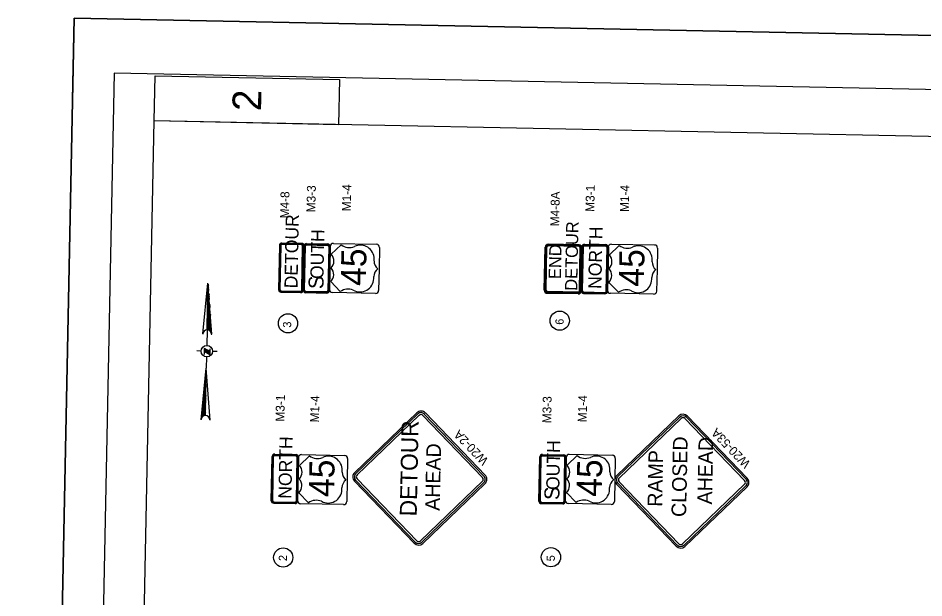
# Model space of a CAD drawing. Extents: x 335726 to 369746, y 119154 to 200788.
# Drawn here: x 335726 to 352294, y 160200 to 170808 of the extents above; entities that cross this region are included whole.
import ezdxf

# ---------------------------------------------------------------- set-up
doc = ezdxf.new("R2010")
doc.units = 0
for name, color, linetype in [('CA-TBLK', 7, 'Continuous'), ('CA-TEXT', 7, 'Continuous'), ('P_RDWY_Text', 7, 'Continuous'), ('P_SGN_Cell', 7, 'Continuous'), ('PLT_Sheet_Border', 7, 'Continuous'), ('PLT_Sheet_Info', 7, 'Continuous')]:
    doc.layers.add(name, color=color, linetype=linetype)

msp = doc.modelspace()

# ---------------------------------------------------------------- linework, layer by layer
at = {"layer": 'CA-TBLK'}
for p, q in [((339106, 165031), (339199, 165960)), ((339182, 165105), (339199, 165960)), ((339197, 165855), (339213, 165869)), ((339212, 165854), (339197, 165840)), ((339198, 165915), (339213, 165914)), ((339213, 165914), (339198, 165900)), ((339198, 165900), (339213, 165899)), ((339213, 165884), (339198, 165885)), ((339198, 165870), (339213, 165884)), ((339213, 165869), (339198, 165870)), ((339271, 165028), (339199, 165960)), ((339199, 165960), (339199, 165960)), ((339199, 165960), (339199, 165960)), ((339199, 165945), (339199, 165945)), ((339199, 165930), (339214, 165929)), ((339214, 165929), (339199, 165930)), ((339193, 165660), (339224, 165689)), ((339225, 165734), (339194, 165705)), ((339225, 165719), (339194, 165690)), ((339194, 165705), (339225, 165719)), ((339194, 165675), (339224, 165704)), ((339224, 165689), (339194, 165675)), ((339195, 165765), (339211, 165779)), ((339211, 165779), (339195, 165765)), ((339210, 165764), (339195, 165750)), ((339195, 165735), (339225, 165764)), ((339225, 165749), (339195, 165735)), ((339195, 165720), (339225, 165734)), ((339212, 165824), (339196, 165810)), ((339211, 165809), (339196, 165795)), ((339196, 165795), (339211, 165809)), ((339196, 165780), (339211, 165794)), ((339197, 165840), (339212, 165839)), ((339212, 165839), (339197, 165825)), ((339197, 165825), (339212, 165824)), ((339190, 165495), (339236, 165539)), ((339236, 165539), (339190, 165510)), ((339190, 165480), (339236, 165524)), ((339236, 165524), (339190, 165495)), ((339222, 165599), (339191, 165570)), ((339222, 165584), (339191, 165555)), ((339191, 165555), (339222, 165584)), ((339236, 165569), (339191, 165525)), ((339191, 165540), (339236, 165569)), ((339191, 165525), (339236, 165554)), ((339192, 165615), (339223, 165644)), ((339192, 165600), (339223, 165629)), ((339223, 165629), (339192, 165615)), ((339222, 165614), (339192, 165585)), ((339192, 165585), (339222, 165614)), ((339224, 165674), (339193, 165660)), ((339193, 165645), (339224, 165674)), ((339223, 165659), (339193, 165630)), ((339186, 165315), (339247, 165359)), ((339247, 165359), (339186, 165315)), ((339233, 165404), (339187, 165360)), ((339187, 165360), (339233, 165404)), ((339248, 165389), (339187, 165330)), ((339187, 165345), (339248, 165389)), ((339187, 165330), (339248, 165374)), ((339188, 165420), (339234, 165464)), ((339188, 165405), (339234, 165449)), ((339234, 165449), (339188, 165420)), ((339188, 165390), (339234, 165434)), ((339234, 165434), (339188, 165390)), ((339233, 165419), (339188, 165375)), ((339189, 165465), (339235, 165494)), ((339235, 165494), (339189, 165450)), ((339235, 165479), (339189, 165435)), ((339189, 165450), (339235, 165479)), ((339235, 165509), (339190, 165480)), ((339245, 165224), (339183, 165165)), ((339183, 165165), (339245, 165224)), ((339259, 165208), (339183, 165135)), ((339183, 165150), (339259, 165208)), ((339183, 165135), (339259, 165193)), ((339184, 165210), (339245, 165269)), ((339184, 165195), (339245, 165254)), ((339245, 165254), (339184, 165195)), ((339245, 165239), (339184, 165180)), ((339246, 165314), (339185, 165255)), ((339185, 165270), (339246, 165314)), ((339246, 165299), (339185, 165240)), ((339185, 165255), (339246, 165299)), ((339185, 165225), (339246, 165284)), ((339245, 165269), (339185, 165225)), ((339186, 165285), (339247, 165344)), ((339247, 165344), (339186, 165300)), ((339247, 165329), (339186, 165285)), ((339182, 165105), (339176, 164820)), ((339182, 165120), (339259, 165178)), ((339259, 165178), (339182, 165120)), ((339258, 165163), (339182, 165105)), ((339197, 165105), (339258, 165163)), ((339258, 165148), (339212, 165104)), ((339212, 165104), (339258, 165133)), ((339258, 165133), (339227, 165089)), ((339257, 165118), (339227, 165089)), ((339227, 165089), (339257, 165118)), ((339242, 165089), (339257, 165103)), ((339257, 165088), (339242, 165074)), ((339242, 165074), (339257, 165088)), ((339256, 165058), (339257, 165073)), ((339256, 165058), (339256, 165058)), ((339256, 165043), (339256, 165043)), ((339256, 165043), (339256, 165043)), ((339256, 165028), (339271, 165028)), ((339257, 165073), (339257, 165073)), ((339069, 164717), (338994, 164719)), ((339130, 164761), (339128, 164656)), ((339129, 164716), (339175, 164745)), ((339160, 164745), (339129, 164716)), ((339129, 164716), (339160, 164745)), ((339129, 164716), (339233, 164654)), ((339130, 164746), (339145, 164761)), ((339145, 164761), (339130, 164746)), ((339130, 164761), (339130, 164761)), ((339234, 164714), (339130, 164761)), ((339160, 164760), (339130, 164731)), ((339175, 164745), (339144, 164701)), ((339144, 164701), (339190, 164730)), ((339190, 164730), (339159, 164700)), ((339159, 164700), (339205, 164729)), ((339174, 164685), (339205, 164729)), ((339205, 164729), (339174, 164700)), ((339234, 164714), (339189, 164685)), ((339189, 164685), (339219, 164714)), ((339219, 164714), (339189, 164685)), ((339203, 164669), (339234, 164699)), ((339234, 164699), (339203, 164669)), ((339235, 164759), (339233, 164654)), ((339279, 164713), (339369, 164711)), ((339172, 164610), (339168, 164400)), ((339218, 164669), (339234, 164684)), ((339234, 164684), (339218, 164669)), ((339233, 164654), (339233, 164669)), ((339074, 163457), (339168, 164400)), ((339151, 163545), (339168, 164400)), ((339167, 164370), (339167, 164370)), ((339239, 163453), (339168, 164400)), ((339168, 164400), (339168, 164400)), ((339168, 164385), (339168, 164385)), ((339168, 164385), (339168, 164385)), ((339164, 164220), (339149, 164220)), ((339149, 164220), (339164, 164205)), ((339149, 164205), (339163, 164175)), ((339164, 164190), (339149, 164205)), ((339150, 164235), (339164, 164220)), ((339165, 164265), (339166, 164280)), ((339165, 164250), (339165, 164265)), ((339165, 164265), (339165, 164265)), ((339165, 164250), (339165, 164235)), ((339165, 164235), (339165, 164250)), ((339166, 164325), (339167, 164340)), ((339166, 164325), (339166, 164325)), ((339166, 164310), (339166, 164310)), ((339166, 164310), (339166, 164295)), ((339166, 164295), (339166, 164280)), ((339166, 164295), (339166, 164295)), ((339167, 164355), (339167, 164355)), ((339167, 164355), (339167, 164355)), ((339167, 164340), (339167, 164340)), ((339130, 164026), (339160, 163995)), ((339160, 163995), (339130, 164026)), ((339131, 164056), (339160, 164025)), ((339131, 164041), (339160, 164010)), ((339160, 164025), (339131, 164041)), ((339161, 164040), (339146, 164070)), ((339146, 164070), (339161, 164040)), ((339147, 164115), (339162, 164085)), ((339162, 164100), (339147, 164115)), ((339147, 164100), (339161, 164070)), ((339161, 164070), (339147, 164100)), ((339161, 164055), (339147, 164085)), ((339163, 164160), (339148, 164175)), ((339148, 164175), (339163, 164160)), ((339163, 164130), (339148, 164160)), ((339148, 164160), (339163, 164145)), ((339148, 164145), (339163, 164130)), ((339148, 164130), (339162, 164100)), ((339162, 164115), (339148, 164130)), ((339163, 164175), (339149, 164190)), ((339112, 163876), (339156, 163830)), ((339112, 163861), (339156, 163815)), ((339156, 163815), (339112, 163861)), ((339157, 163845), (339113, 163891)), ((339157, 163875), (339128, 163921)), ((339157, 163860), (339128, 163906)), ((339128, 163906), (339157, 163875)), ((339128, 163891), (339157, 163845)), ((339159, 163935), (339129, 163981)), ((339129, 163981), (339159, 163950)), ((339129, 163966), (339159, 163935)), ((339129, 163951), (339158, 163905)), ((339158, 163920), (339129, 163951)), ((339158, 163905), (339129, 163936)), ((339129, 163936), (339158, 163890)), ((339159, 163980), (339130, 164011)), ((339159, 163965), (339130, 163996)), ((339130, 163996), (339159, 163965)), ((339153, 163665), (339109, 163726)), ((339109, 163726), (339153, 163680)), ((339153, 163650), (339109, 163711)), ((339109, 163711), (339153, 163650)), ((339109, 163696), (339153, 163635)), ((339110, 163771), (339154, 163710)), ((339154, 163725), (339110, 163771)), ((339110, 163756), (339154, 163695)), ((339154, 163710), (339110, 163756)), ((339153, 163680), (339110, 163741)), ((339156, 163785), (339111, 163831)), ((339111, 163816), (339155, 163770)), ((339155, 163770), (339111, 163816)), ((339155, 163740), (339111, 163801)), ((339111, 163801), (339155, 163755)), ((339111, 163786), (339155, 163740)), ((339112, 163846), (339156, 163800)), ((339156, 163800), (339112, 163846)), ((339090, 163531), (339105, 163516)), ((339090, 163516), (339090, 163531)), ((339091, 163576), (339120, 163531)), ((339135, 163531), (339091, 163576)), ((339120, 163531), (339091, 163561)), ((339105, 163516), (339091, 163546)), ((339091, 163546), (339105, 163531)), ((339151, 163545), (339092, 163621)), ((339092, 163621), (339151, 163560)), ((339092, 163606), (339151, 163545)), ((339092, 163591), (339136, 163546)), ((339151, 163545), (339092, 163591)), ((339093, 163681), (339152, 163620)), ((339152, 163620), (339093, 163681)), ((339093, 163666), (339152, 163590)), ((339152, 163605), (339093, 163666)), ((339152, 163590), (339093, 163651)), ((339151, 163575), (339093, 163636)), ((339093, 163636), (339151, 163575)), ((339074, 163472), (339074, 163472)), ((339075, 163517), (339090, 163501)), ((339075, 163502), (339090, 163501)), ((339090, 163501), (339075, 163502)), ((339075, 163487), (339075, 163487)), ((339075, 163487), (339075, 163487))]:
    msp.add_line(p, q, dxfattribs=at)
msp.add_circle((339178, 164713), 104, dxfattribs=at)
for centre, start, end in [((339184, 165026), 358.8468, 178.8468), ((339184, 165026), 178.84682431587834, 178.8468298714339), ((339152, 163461), 358.8468, 178.8468), ((339152, 163461), 358.84700764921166, 358.8470132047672)]:
    msp.add_arc(centre, 78.3, start, end, dxfattribs=at)
at = {"layer": 'CA-TEXT'}
for centre in [(340662, 165223), (345633, 165272), (340575, 160939), (345472, 160944)]:
    msp.add_circle(centre, 176, dxfattribs=at)
at = {"layer": 'P_RDWY_Text'}
msp.add_lwpolyline([(335726, 119818), (336753, 170808), (369746, 170144), (368719, 119154)], close=True, dxfattribs=at)
at = {"layer": 'P_SGN_Cell'}
for p, q in [((341002, 166684), (341392, 166676)), ((341493, 166686), (342281, 166670)), ((340940, 165830), (340956, 166640)), ((340951, 165830), (340967, 166640)), ((340966, 165830), (340982, 166640)), ((341002, 166673), (341392, 166665)), ((341002, 166658), (341391, 166650)), ((341410, 166631), (341393, 165821)), ((341425, 166631), (341408, 165821)), ((341436, 166631), (341420, 165821)), ((341420, 165843), (341436, 166631)), ((341636, 166661), (341454, 166486)), ((342336, 166612), (342328, 166219)), ((342336, 166612), (342336, 166612)), ((345351, 165830), (345367, 166617)), ((345365, 165829), (345381, 166617)), ((345384, 165829), (345400, 166616)), ((345986, 166628), (345423, 166639)), ((345986, 166661), (345424, 166672)), ((345986, 166647), (345424, 166658)), ((345993, 165817), (346009, 166604)), ((346012, 165816), (346028, 166604)), ((346026, 165816), (346042, 166627)), ((346026, 165816), (346042, 166604)), ((346037, 165817), (346053, 166626)), ((346052, 165816), (346068, 166626)), ((346087, 166644), (346477, 166637)), ((346088, 166671), (346478, 166663)), ((346088, 166659), (346478, 166652)), ((346496, 166617), (346479, 165808)), ((346511, 166617), (346494, 165807)), ((346506, 165830), (346522, 166617)), ((346522, 166617), (346506, 165807)), ((346722, 166648), (346540, 166473)), ((346579, 166672), (347367, 166657)), ((347422, 166599), (347414, 166205)), ((347422, 166599), (347422, 166599)), ((342238, 166364), (342238, 166399)), ((347324, 166350), (347324, 166386)), ((342328, 166219), (342320, 165825)), ((347414, 166205), (347406, 165812)), ((342231, 166042), (342232, 166078)), ((347317, 166029), (347318, 166064)), ((341444, 165986), (341619, 165804)), ((346530, 165973), (346705, 165791)), ((340984, 165811), (341374, 165803)), ((340984, 165796), (341374, 165788)), ((340984, 165785), (341374, 165777)), ((342263, 165770), (341475, 165786)), ((345969, 165775), (345406, 165786)), ((345968, 165761), (345406, 165772)), ((345969, 165794), (345407, 165805)), ((346070, 165797), (346460, 165789)), ((346070, 165782), (346460, 165774)), ((346070, 165771), (346460, 165763)), ((347349, 165757), (346561, 165773)), ((340357, 161978), (340373, 162788)), ((340368, 161978), (340384, 162788)), ((340383, 161978), (340399, 162787)), ((340419, 162832), (340809, 162824)), ((340419, 162821), (340809, 162813)), ((340419, 162806), (340808, 162798)), ((340827, 162779), (340811, 161969)), ((340842, 162779), (340826, 161969)), ((340853, 162778), (340837, 161968)), ((340837, 161980), (340853, 162767)), ((341053, 162798), (340871, 162623)), ((340910, 162822), (341698, 162806)), ((341753, 162749), (341745, 162355)), ((341753, 162749), (341753, 162749)), ((345253, 161971), (345270, 162781)), ((345265, 161971), (345281, 162781)), ((345280, 161971), (345296, 162781)), ((345315, 162814), (345705, 162806)), ((345315, 162799), (345705, 162791)), ((345316, 162825), (345706, 162817)), ((345723, 162772), (345707, 161962)), ((345738, 162772), (345722, 161962)), ((345750, 162771), (345733, 161962)), ((345734, 161984), (345750, 162771)), ((345950, 162802), (345768, 162627)), ((345807, 162827), (346594, 162811)), ((346649, 162753), (346641, 162360)), ((346649, 162753), (346649, 162753)), ((341654, 162500), (341655, 162536)), ((346551, 162504), (346552, 162540)), ((341648, 162179), (341649, 162214)), ((341745, 162355), (341737, 161962)), ((346545, 162183), (346545, 162219)), ((346641, 162360), (346634, 161966)), ((340861, 162123), (341036, 161941)), ((345758, 162127), (345933, 161945)), ((340401, 161959), (340791, 161951)), ((340401, 161944), (340791, 161936)), ((340401, 161932), (340791, 161924)), ((341679, 161907), (340892, 161922)), ((345297, 161925), (345687, 161918)), ((345298, 161952), (345688, 161944)), ((345298, 161937), (345688, 161929)), ((346576, 161911), (345789, 161927))]:
    msp.add_line(p, q, dxfattribs=at)
for points in [[(340912, 166686), (340552, 166693)], [(340912, 166674), (340552, 166682)], [(340506, 166649), (340490, 165839)], [(340517, 166648), (340501, 165839)], [(340532, 166648), (340516, 165838)], [(340912, 166659), (340552, 166667)], [(340914, 165830), (340930, 166640)], [(340929, 165830), (340945, 166640)], [(340940, 165830), (340956, 166640)], [(340534, 165804), (340894, 165797)], [(340534, 165793), (340894, 165786)], [(340535, 165819), (340894, 165812)], [(343018, 163586), (341882, 162495)], [(343038, 163565), (341902, 162474)], [(343063, 163540), (341927, 162449)], [(344221, 162403), (343130, 163539)], [(344247, 162428), (343156, 163563)], [(344267, 162448), (343177, 163583)], [(347812, 163530), (346676, 162439)], [(347832, 163509), (346696, 162418)], [(347856, 163483), (346721, 162392)], [(349015, 162347), (347924, 163482)], [(349041, 162372), (347950, 163507)], [(349061, 162391), (347970, 163527)], [(341926, 162380), (343017, 161244)], [(341879, 162336), (342970, 161200)], [(341900, 162356), (342991, 161220)], [(343085, 161243), (344221, 162334)], [(343109, 161217), (344245, 162308)], [(343129, 161197), (344265, 162288)], [(346673, 162280), (347764, 161144)], [(346693, 162299), (347784, 161163)], [(346719, 162324), (347810, 161188)], [(347878, 161187), (349014, 162278)], [(347903, 161161), (349039, 162252)], [(347923, 161140), (349059, 162231)]]:
    msp.add_lwpolyline(points, dxfattribs=at)
for centre, radius, start, end in [((340551, 166648), 45, 88.8468, 178.8468), ((340551, 166648), 33.7, 88.8468, 178.8468), ((340911, 166641), 45, 358.8468, 88.8468), ((341001, 166639), 45, 88.8462, 178.8462), ((341391, 166631), 45, 358.8462, 88.8462), ((341492, 166629), 56.2, 88.8462, 178.8462), ((340551, 166648), 18.7, 88.8468, 178.8468), ((340911, 166641), 33.7, 358.8468, 88.8468), ((340911, 166641), 18.7, 358.8468, 88.8468), ((341001, 166639), 33.7, 88.8462, 178.8462), ((341001, 166639), 18.7, 88.8462, 178.8462), ((341391, 166631), 18.7, 358.8462, 88.8462), ((341391, 166631), 33.7, 358.8462, 88.8462), ((341786, 166861), 250, 233.1143, 291.9873), ((341988, 166404), 250, 358.8462, 115.6928), ((342280, 166614), 56.2, 358.8462, 88.8462), ((345423, 166616), 56.2, 88.8468, 178.8468), ((345423, 166616), 42.2, 88.8468, 178.8468), ((345423, 166616), 23.4, 88.8468, 178.8468), ((345985, 166605), 56.2, 358.8468, 88.8468), ((345985, 166605), 42.2, 358.8468, 88.8468), ((345985, 166605), 23.4, 358.8468, 88.8468), ((346087, 166626), 45, 88.8462, 178.8462), ((346087, 166626), 33.7, 88.8462, 178.8462), ((346087, 166626), 18.7, 88.8462, 178.8462), ((346477, 166618), 18.7, 358.8462, 88.8462), ((346477, 166618), 45, 358.8462, 88.8462), ((346477, 166618), 33.7, 358.8462, 88.8462), ((346578, 166616), 56.2, 88.8462, 178.8462), ((346872, 166848), 250, 233.1143, 291.9873), ((347074, 166391), 250, 358.8462, 115.6928), ((347366, 166600), 56.2, 358.8462, 88.8462), ((341324, 166364), 179, 314.4191, 43.2734), ((342418, 166361), 181, 179.1885, 231.634), ((346410, 166351), 179, 314.4191, 43.2734), ((347504, 166348), 181, 179.1885, 231.634), ((341319, 166114), 179, 314.4191, 43.2734), ((342413, 166073), 181, 126.0584, 178.5039), ((346405, 166101), 179, 314.4191, 43.2734), ((347498, 166060), 181, 126.0584, 178.5039), ((341981, 166047), 250, 240.0981, 358.8463), ((347067, 166034), 250, 240.0981, 358.8463), ((341762, 165599), 250, 67.7159, 124.7982), ((340535, 165838), 45, 178.8468, 268.8468), ((340535, 165838), 33.7, 178.8468, 268.8468), ((340535, 165838), 18.7, 178.8468, 268.8468), ((340535, 165838), 18.7, 178.8468, 186.1883), ((340895, 165831), 45, 268.8468, 358.8468), ((340895, 165831), 33.7, 268.8468, 358.8468), ((340895, 165831), 18.7, 268.8468, 358.8468), ((340985, 165829), 45, 179.6119, 268.8462), ((340985, 165829), 33.7, 178.8462, 268.8462), ((340985, 165829), 18.7, 178.8462, 268.8462), ((341375, 165822), 33.7, 268.8462, 358.8462), ((341375, 165822), 18.7, 268.8462, 358.8462), ((341375, 165822), 45, 268.8462, 358.8462), ((341476, 165842), 56.2, 178.8462, 268.8462), ((342264, 165826), 56.2, 268.8462, 358.8462), ((345407, 165829), 56.2, 178.8468, 268.8468), ((345407, 165829), 42.2, 178.8468, 268.8468), ((345407, 165829), 23.4, 178.8468, 268.8468), ((345407, 165829), 23.4, 178.8468, 187.6911), ((345970, 165817), 56.2, 268.8468, 358.8468), ((345970, 165817), 23.4, 268.8468, 358.8468), ((345970, 165817), 42.2, 268.8468, 358.8468), ((346071, 165816), 45, 179.6119, 268.8462), ((346071, 165816), 33.7, 178.8462, 268.8462), ((346071, 165816), 18.7, 178.8462, 268.8462), ((346461, 165808), 18.7, 268.8462, 358.8462), ((346461, 165808), 33.7, 268.8462, 358.8462), ((346461, 165808), 45, 268.8462, 358.8462), ((346562, 165829), 56.2, 178.8462, 268.8462), ((346848, 165586), 250, 67.7159, 124.7982), ((347350, 165813), 56.2, 268.8462, 358.8462), ((343096, 163505), 112, 43.8468, 133.8468), ((343096, 163505), 83.9, 43.8468, 133.8468), ((343096, 163505), 48.2, 43.8468, 133.8468), ((347890, 163448), 112, 43.8462, 133.8462), ((347890, 163448), 83.9, 43.8462, 133.8462), ((347890, 163448), 48.2, 43.8462, 133.8462), ((340418, 162787), 45, 88.8462, 178.8462), ((340418, 162787), 33.7, 88.8462, 178.8462), ((340418, 162787), 18.7, 88.8462, 178.8462), ((340808, 162779), 18.7, 358.8462, 88.8462), ((340808, 162779), 45, 358.8462, 88.8462), ((340808, 162779), 33.7, 358.8462, 88.8462), ((340909, 162766), 56.2, 88.8462, 178.8462), ((341203, 162998), 250, 233.1143, 291.9873), ((341405, 162541), 250, 358.8462, 115.6928), ((341696, 162750), 56.2, 358.8462, 88.8462), ((345315, 162780), 45, 88.8462, 178.8462), ((345315, 162780), 33.7, 88.8462, 178.8462), ((345315, 162780), 18.7, 88.8462, 178.8462), ((345705, 162772), 45, 358.8462, 88.8462), ((345705, 162772), 33.7, 358.8462, 88.8462), ((345705, 162772), 18.7, 358.8462, 88.8462), ((345806, 162770), 56.2, 88.8462, 178.8462), ((346100, 163002), 250, 233.1143, 291.9873), ((346302, 162545), 250, 358.8462, 115.6928), ((346593, 162755), 56.2, 358.8462, 88.8462), ((340741, 162501), 179, 314.4191, 43.2734), ((345638, 162505), 179, 314.4191, 43.2734), ((340736, 162251), 179, 314.4191, 43.2734), ((341835, 162497), 181, 179.1885, 231.634), ((341960, 162414), 112, 133.8449, 223.8468), ((341960, 162414), 83.9, 133.8449, 223.8468), ((341960, 162414), 48.2, 133.8449, 223.8468), ((344187, 162369), 48.2, 313.854, 44.4977), ((344187, 162369), 83.9, 313.854, 44.4977), ((344187, 162369), 112, 313.854, 44.4977), ((345633, 162255), 179, 314.4191, 43.2734), ((346732, 162502), 181, 179.1885, 231.634), ((346754, 162357), 112, 133.8443, 223.8462), ((346754, 162357), 83.9, 133.8443, 223.8462), ((346754, 162357), 48.2, 133.8443, 223.8462), ((348981, 162313), 83.9, 313.8534, 44.4971), ((348981, 162313), 112, 313.8534, 44.4971), ((341829, 162210), 181, 126.0584, 178.5039), ((346726, 162214), 181, 126.0584, 178.5039), ((348981, 162313), 48.2, 313.8534, 44.4971), ((341398, 162184), 250, 240.0981, 358.8463), ((346295, 162188), 250, 240.0981, 358.8463), ((340402, 161977), 45, 179.6119, 268.8462), ((340402, 161977), 33.7, 178.8462, 268.8462), ((340402, 161977), 18.7, 178.8462, 268.8462), ((340792, 161969), 33.7, 268.8462, 358.8462), ((340792, 161969), 18.7, 268.8462, 358.8462), ((340792, 161969), 45, 268.8462, 358.8462), ((340893, 161979), 56.2, 178.8462, 268.8462), ((341179, 161736), 250, 67.7159, 124.7982), ((341681, 161963), 56.2, 268.8462, 358.8462), ((345298, 161970), 45, 179.6119, 268.8462), ((345298, 161970), 33.7, 178.8462, 268.8462), ((345298, 161970), 18.7, 178.8462, 268.8462), ((345688, 161963), 45, 268.8462, 358.8462), ((345688, 161963), 33.7, 268.8462, 358.8462), ((345688, 161963), 18.7, 268.8462, 358.8462), ((345790, 161983), 56.2, 178.8462, 268.8462), ((346075, 161740), 250, 67.7159, 124.7982), ((346577, 161967), 56.2, 268.8462, 358.8462), ((343051, 161278), 83.9, 223.8468, 313.8468), ((343051, 161278), 48.2, 223.8468, 313.8468), ((343051, 161278), 112, 223.8468, 313.8468), ((347845, 161222), 112, 223.8462, 313.8462), ((347845, 161222), 83.9, 223.8462, 313.8462), ((347845, 161222), 48.2, 223.8462, 313.8462)]:
    msp.add_arc(centre, radius, start, end, dxfattribs=at)
at = {"layer": 'PLT_Sheet_Border'}
for points in [[(368719, 119154), (369746, 170144), (336753, 170808), (335726, 119818)], [(367976, 119529), (368976, 169169), (337483, 169803), (336483, 120163)]]:
    msp.add_lwpolyline(points, close=True, dxfattribs=at)
at = {"layer": 'PLT_Sheet_Info'}
for p, q in [((336722, 169308), (336753, 170808)), ((338252, 170778), (336753, 170808)), ((337264, 121685), (338215, 168926)), ((368209, 168322), (338215, 168926))]:
    msp.add_line(p, q, dxfattribs=at)
msp.add_lwpolyline([(338215, 168926), (338232, 169751), (341606, 169683), (341589, 168858)], close=True, dxfattribs=at)

# ---------------------------------------------------------------- texts
at = {"layer": 'CA-TEXT'}
for s, p in [('3', (340720, 165143)), ('6', (345703, 165196)), ('2', (340643, 160872)), ('5', (345542, 160868))]:
    msp.add_text(s, height=150, rotation=88.8468, dxfattribs=at).set_placement(p)
at = {"layer": 'P_SGN_Cell'}
for s, height, rotation, p in [('M3-3', 162, 88.8462, (341162, 167254)), ('M1-4', 162, 88.8462, (341811, 167272)), ('M3-1', 162, 88.8462, (346265, 167263)), ('M1-4', 162, 88.8462, (346897, 167259)), ('M4-8', 162, 88.8468, (340679, 167142)), ('M4-8A', 162, 88.8468, (345622, 166997)), ('DETOUR', 240, 88.8468, (340836, 165862)), ('DETOUR', 225, 88.8468, (345952, 165817)), ('OUTH', 240, 88.8462, (341311, 166032)), ('NORTH', 240, 88.8462, (346394, 165851)), ('45', 460, 88.8462, (342086, 165905)), ('END', 225, 88.8468, (345655, 166031)), ('45', 460, 88.8462, (347172, 165892)), ('S', 274, 88.8462, (341311, 165848)), ('M3-1', 162, 88.8462, (340596, 163424)), ('M1-4', 162, 88.8462, (341228, 163409)), ('M3-3', 162, 88.8462, (345476, 163395)), ('M1-4', 162, 88.8462, (346125, 163413)), ('DETOUR', 310.7, 88.8468, (343017, 161689)), ('W20-2A', 162, 133.8468, (344339, 162723)), ('W20-53A', 162, 133.8468, (349132, 162667)), ('NORTH', 240, 88.8462, (340725, 162012)), ('OUTH', 240, 88.8462, (345625, 162172)), ('CLOSED', 267.9, 88.8462, (347944, 161678)), ('AHEAD', 267.9, 88.8462, (348417, 161908)), ('AHEAD', 267.9, 88.8468, (343438, 161791)), ('RAMP', 267.9, 88.8462, (347506, 161865)), ('45', 460, 88.8462, (341503, 162042)), ('45', 460, 88.8462, (346400, 162046)), ('S', 274, 88.8462, (345625, 161989))]:
    msp.add_text(s, height=height, rotation=rotation, dxfattribs=at).set_placement(p)
at = {"layer": 'PLT_Sheet_Info'}
msp.add_text('2', height=525, rotation=88.8462, dxfattribs=at).set_placement((340169, 169103))

doc.saveas('drawing.dxf')
